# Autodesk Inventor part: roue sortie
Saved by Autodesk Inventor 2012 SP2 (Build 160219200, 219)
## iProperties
Created: 2013-04
Part Number: roue sortie
Material: Default
Document SubType Name: Modeling
Designer: papa
Density: 1 g/cm^3
Mass: 68.576 g
Surface Area: 144.615 cm^2
Volume: 68.576 cm^3
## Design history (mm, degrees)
node "roue sortie1"
node "roue sortie"
node "Base1"
